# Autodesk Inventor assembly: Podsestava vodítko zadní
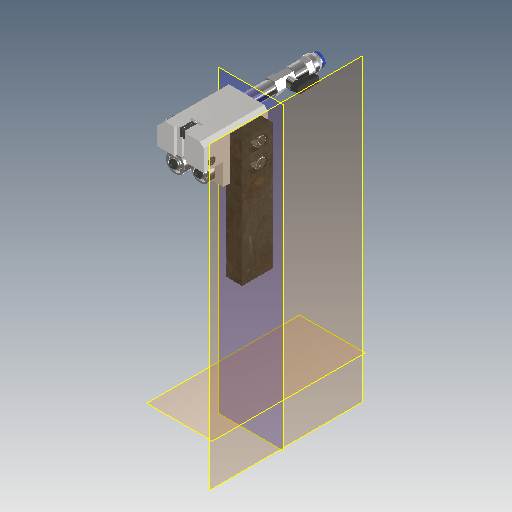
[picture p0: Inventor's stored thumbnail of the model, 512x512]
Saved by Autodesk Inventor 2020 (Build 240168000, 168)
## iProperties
Created: 2025-04
Part Number: Podsestava vodítko zadní
Document SubType Name: Assembly
Designer: doma
Mass: 2952.38 g
Surface Area: 907.876 cm^2
Volume: 382.625 cm^3
Density: 7.71611 g/cm^3
Author: doma
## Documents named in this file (17)
- C:\Users\doma\Desktop\Pásovka záloha\Workgroups\NotInProject\Podsestava vodítko zadní.iam
- C:\Users\doma\Desktop\Pásovka záloha\Workgroups\NotInProject\Vedení vodítek pásovina zadní.ipt
- C:\Users\doma\Desktop\Pásovka záloha\Workgroups\NotInProject\Vodítko zadní.ipt
- C:\Users\doma\Desktop\Pásovka záloha\Workgroups\NotInProject\Excentr vodících ložisek 1.ipt
- C:\Users\doma\Documents\Inventor\Content Center Files\R2020\cs-CZ\CSN 02 4630\CSN 02 4630 - 609.ipt
- C:\Users\doma\Desktop\Pásovka záloha\Workgroups\NotInProject\Tvrdokovová destička.ipt
- C:\Users\doma\Desktop\Pásovka záloha\Workgroups\NotInProject\Kruhová tvrdokovová destička.ipt
- C:\Users\doma\Desktop\Pásovka záloha\Workgroups\NotInProject\Přechodka.ipt
- C:\Users\doma\Desktop\Pásovka záloha\Workgroups\NotInProject\Trubka chlazení.ipt
- C:\Users\doma\Desktop\Pásovka záloha\Workgroups\NotInProject\Ventil šroubovací.ipt
- C:\Users\doma\Documents\Inventor\Content Center Files\R2020\cs-CZ\ISO 4762(2)\ISO 4762 - M8 x 30ISO.ipt
- C:\Users\doma\Documents\Inventor\Content Center Files\R2020\cs-CZ\ISO 4762(2)\ISO 4762 - M6 x 20ISO.ipt
- C:\Users\doma\Documents\Inventor\Content Center Files\R2020\cs-CZ\ISO 4762(2)\ISO 4762 - M8 x 16ISO.ipt
- C:\Users\doma\Documents\Inventor\Content Center Files\R2020\cs-CZ\CSN 02 1187\CSN 02 1187 - M4 x 0,7 x 16.ipt
- C:\Users\doma\Desktop\Pásovka záloha\Workgroups\NotInProject\Excentr vodících ložisek 2.ipt
- C:\Users\doma\Documents\Inventor\Content Center Files\R2020\cs-CZ\CSN 02 1703\CSN 02 1703 - 6,4.ipt
- C:\Users\doma\Documents\Inventor\Content Center Files\R2020\cs-CZ\ISO 7380-1\ISO 7380-1 - M6 x 10.ipt
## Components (25 placed, 16 different names)
1. Vedení vodítek pásovina zadní:1 — Proti sobě:19, Stejný směr:6
2. Vodítko zadní:1 — Proti sobě:17, Proti sobě:18, Úhel:3, Proti sobě:20, Proti sobě:21, Stejný směr:4, Proti sobě:22, Proti sobě:23, Stejný směr:7
3. Excentr vodících ložisek 1:1
4. CSN 02 4630 609:1
5. Tvrdokovová destička:1
6. Tvrdokovová destička:2
7. Kruhová tvrdokovová destička:1
8. Přechodka:1
9. Trubka chlazení:1 — Proti sobě:17, Proti sobě:18
10. Ventil šroubovací:1 — Úhel:3
11. Excentr vodících ložisek 2:1
12. CSN 02 4630 609:2
13. CSN 02 4630 609:3
14. ISO 4762 M8 x 30:1
15. ISO 4762 M8 x 30:2
16. ISO 4762 M6 x 20:1
17. ISO 4762 M8 x 16:1 — Proti sobě:21
18. ISO 4762 M8 x 16:2 — Proti sobě:19, Proti sobě:20
19. CSN 02 1187 M4 x 16:2 — Stejný směr:3, Stejný směr:4, Proti sobě:23
20. CSN 02 1187 M4 x 16:1 — Stejný směr:3, Proti sobě:22
21. ISO 4762 M6 x 20:2
22. CSN 02 1703 6,4:1
23. CSN 02 1703 6,4:2
24. ISO 7380-1 M6 x 10:1
25. ISO 7380-1 M6 x 10:2
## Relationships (12: Mate 7, Flush 4, Angle 1)
- Proti sobě:17 [Mate]: Vodítko zadní:1 ↔ Trubka chlazení:1
- Proti sobě:18 [Mate]: Vodítko zadní:1 ↔ Trubka chlazení:1
- Úhel:3 [Angle]: Vodítko zadní:1 ↔ Ventil šroubovací:1
- Proti sobě:19 [Mate]: Vedení vodítek pásovina zadní:1 ↔ ISO 4762 M8 x 16:2
- Proti sobě:20 [Mate]: Vodítko zadní:1 ↔ ISO 4762 M8 x 16:2
- Proti sobě:21 [Mate]: Vodítko zadní:1 ↔ ISO 4762 M8 x 16:1
- Stejný směr:3 [Flush]: CSN 02 1187 M4 x 16:2 ↔ CSN 02 1187 M4 x 16:1
- Stejný směr:4 [Flush]: Vodítko zadní:1 ↔ CSN 02 1187 M4 x 16:2
- Proti sobě:22 [Mate]: Vodítko zadní:1 ↔ CSN 02 1187 M4 x 16:1
- Proti sobě:23 [Mate]: Vodítko zadní:1 ↔ CSN 02 1187 M4 x 16:2
- Stejný směr:6 [Flush]: Vedení vodítek pásovina zadní:1
- Stejný směr:7 [Flush]: Vodítko zadní:1
